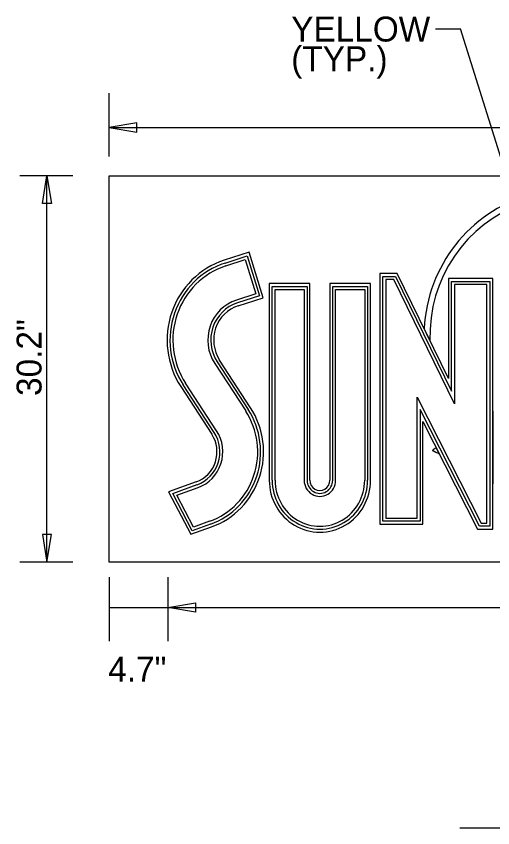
# Model space of a CAD drawing. Extents: x 10268197 to 10268738, y 2141503 to 2142677.
# Drawn here: x 10268621.93 to 10268635.31, y 2142399.46 to 2142422.24 of the extents above; entities that cross this region are included whole.
import ezdxf

# ---------------------------------------------------------------- set-up
doc = ezdxf.new("R2010")
doc.units = 0
for name, color, linetype in [('1', 7, 'Continuous'), ('Default', 7, 'Continuous'), ('GSDims', 7, 'Continuous')]:
    doc.layers.add(name, color=color, linetype=linetype)

msp = doc.modelspace()

# ---------------------------------------------------------------- linework, layer by layer
at = {"layer": '1'}
for p in [(10268633.707, 2142421.886), (10268636.311, 2142415.796)]:
    msp.add_line(p, (10268634.409, 2142421.886), dxfattribs=at)
at = {"layer": 'Default'}
for p, q in [((10268627.797, 2142415.309), (10268628.418, 2142415.51)), ((10268628.418, 2142415.51), (10268628.762, 2142414.392)), ((10268627.822, 2142415.23), (10268628.365, 2142415.405)), ((10268627.822, 2142415.23), (10268628.365, 2142415.405)), ((10268628.365, 2142415.405), (10268628.66, 2142414.447)), ((10268628.365, 2142415.405), (10268628.66, 2142414.447)), ((10268632.143, 2142415.013), (10268632.143, 2142407.978)), ((10268632.225, 2142408.062), (10268632.225, 2142414.929)), ((10268632.306, 2142414.845), (10268632.306, 2142408.146)), ((10268632.532, 2142414.845), (10268632.306, 2142414.845)), ((10268634.234, 2142411.355), (10268632.532, 2142414.845)), ((10268629.119, 2142409.212), (10268629.119, 2142414.655)), ((10268629.119, 2142414.655), (10268630.1, 2142414.655)), ((10268629.201, 2142409.212), (10268629.201, 2142414.572)), ((10268629.201, 2142414.572), (10268630.018, 2142414.572)), ((10268629.201, 2142409.212), (10268629.201, 2142414.572)), ((10268629.201, 2142414.572), (10268630.018, 2142414.572)), ((10268630.018, 2142414.572), (10268630.018, 2142409.212)), ((10268630.018, 2142414.572), (10268630.018, 2142409.212)), ((10268630.1, 2142414.655), (10268630.1, 2142409.212)), ((10268630.819, 2142409.212), (10268630.819, 2142414.655)), ((10268630.819, 2142414.655), (10268631.799, 2142414.655)), ((10268630.9, 2142409.212), (10268630.9, 2142414.572)), ((10268630.9, 2142414.572), (10268631.717, 2142414.572)), ((10268630.9, 2142409.212), (10268630.9, 2142414.572)), ((10268630.9, 2142414.572), (10268631.717, 2142414.572)), ((10268631.717, 2142414.572), (10268631.717, 2142409.212)), ((10268631.717, 2142414.572), (10268631.717, 2142409.212)), ((10268631.799, 2142414.655), (10268631.799, 2142409.212)), ((10268634.234, 2142414.711), (10268634.234, 2142411.355)), ((10268635.149, 2142414.711), (10268634.234, 2142414.711)), ((10268635.149, 2142408.012), (10268635.149, 2142414.711)), ((10268628.66, 2142414.447), (10268628.117, 2142414.271)), ((10268628.66, 2142414.447), (10268628.117, 2142414.271)), ((10268628.762, 2142414.392), (10268628.142, 2142414.191)), ((10268633.389, 2142413.463), (10268633.549, 2142413.136)), ((10268627.575, 2142412.54), (10268628.444, 2142411.203)), ((10268628.512, 2142411.25), (10268627.643, 2142412.586)), ((10268627.507, 2142412.493), (10268628.376, 2142411.157)), ((10268627.507, 2142412.493), (10268628.376, 2142411.157)), ((10268626.555, 2142411.843), (10268627.424, 2142410.506)), ((10268627.492, 2142410.553), (10268626.623, 2142411.89)), ((10268627.56, 2142410.599), (10268626.691, 2142411.936)), ((10268627.56, 2142410.599), (10268626.691, 2142411.936)), ((10268633.189, 2142408.146), (10268633.189, 2142411.542)), ((10268633.189, 2142411.542), (10268634.987, 2142408.012)), ((10268635.313, 2142411.156), (10268635.313, 2142409.116)), ((10268633.817, 2142409.946), (10268633.726, 2142410.126)), ((10268626.327, 2142408.844), (10268627.013, 2142409.089)), ((10268626.444, 2142408.798), (10268627.04, 2142409.01)), ((10268626.444, 2142408.798), (10268627.04, 2142409.01)), ((10268626.872, 2142407.797), (10268626.327, 2142408.844)), ((10268626.911, 2142407.9), (10268626.444, 2142408.798)), ((10268626.911, 2142407.9), (10268626.444, 2142408.798)), ((10268627.388, 2142407.982), (10268626.872, 2142407.797)), ((10268627.362, 2142408.061), (10268626.911, 2142407.9)), ((10268627.362, 2142408.061), (10268626.911, 2142407.9)), ((10268632.306, 2142408.146), (10268633.189, 2142408.146)), ((10268634.987, 2142408.012), (10268635.149, 2142408.012)), ((10268653.948, 2142406.917), (10268624.544, 2142406.917)), ((10268634.39, 2142399.458), (10268644.821, 2142399.458))]:
    msp.add_line(p, q, dxfattribs=at)
for points in [[(10268624.544, 2142406.917), (10268624.544, 2142417.76), (10268653.948, 2142417.76), (10268653.948, 2142406.917)], [(10268628.166, 2142414.112), (10268628.865, 2142414.338), (10268628.471, 2142415.615), (10268627.773, 2142415.389)], [(10268632.143, 2142407.978), (10268633.352, 2142407.978), (10268633.352, 2142410.859), (10268634.888, 2142407.844), (10268635.313, 2142407.844), (10268635.313, 2142414.879), (10268634.071, 2142414.879), (10268634.071, 2142412.065), (10268632.633, 2142415.013), (10268632.143, 2142415.013)], [(10268632.225, 2142414.929), (10268632.583, 2142414.929), (10268634.153, 2142411.71), (10268634.153, 2142414.795), (10268635.231, 2142414.795), (10268635.231, 2142407.928), (10268634.937, 2142407.928), (10268633.27, 2142411.2), (10268633.27, 2142408.062), (10268632.225, 2142408.062)], [(10268630.181, 2142409.212), (10268630.181, 2142414.739), (10268629.038, 2142414.739), (10268629.038, 2142409.212)], [(10268631.88, 2142409.212), (10268631.88, 2142414.739), (10268630.737, 2142414.739), (10268630.737, 2142409.212)], [(10268626.986, 2142409.168), (10268626.21, 2142408.891), (10268626.832, 2142407.695), (10268627.415, 2142407.903)]]:
    msp.add_lwpolyline(points, dxfattribs=at)
msp.add_lwpolyline([(10268634.234, 2142414.711), (10268634.234, 2142411.355), (10268632.532, 2142414.845), (10268632.306, 2142414.845), (10268632.306, 2142408.146), (10268633.189, 2142408.146), (10268633.189, 2142411.542), (10268634.987, 2142408.012), (10268635.149, 2142408.012), (10268635.149, 2142414.711)], close=True, dxfattribs=at)
for centre, major_axis, ratio, start_param, end_param in [((10268637.386, 2142413.254), (0, 4.102), 0.97582, 5.303349, 7.802858), ((10268637.386, 2142413.254), (0, 4.102), 0.97582, 5.303349, 7.802858), ((10268637.386, 2142413.254), (0, 3.935), 0.97582, 5.332201, 7.884008), ((10268637.386, 2142413.254), (0, 3.935), 0.97582, 5.332201, 7.884008), ((10268628.464, 2142413.147), (0, 2.351), 0.97582, 0.306207, 2.15869), ((10268628.464, 2142413.147), (0, 2.268), 0.97582, 0.306207, 2.15869), ((10268628.463, 2142413.147), (0, 2.184), 0.975477, 0.305879, 2.158799), ((10268628.463, 2142413.147), (0, 2.184), 0.975477, 0.305879, 2.158799), ((10268628.463, 2142413.147), (0, 1.179), 0.975477, 0.305879, 2.158799), ((10268628.463, 2142413.147), (0, 1.179), 0.975477, 0.305879, 2.158799), ((10268628.464, 2142413.147), (0, 1.095), 0.97582, 0.306207, 2.15869), ((10268628.464, 2142413.147), (0, 1.011), 0.97582, 0.306207, 2.15869), ((10268637.386, 2142413.252), (0, -3.935), 0.97582, 4.712389, 4.712389), ((10268626.7, 2142410.011), (0, -2.065), 0.975477, 0.334737, 2.158799), ((10268626.7, 2142410.011), (0, -2.065), 0.975477, 0.334737, 2.158799), ((10268626.699, 2142410.011), (0, 2.149), 0.97582, 3.476656, 5.300276), ((10268626.699, 2142410.011), (0, 2.233), 0.97582, 3.476656, 5.300276), ((10268626.699, 2142410.011), (0, 0.893), 0.97582, 3.476661, 5.300276), ((10268626.699, 2142410.011), (0, 0.977), 0.97582, 3.476661, 5.300276), ((10268626.7, 2142410.011), (0, -1.06), 0.975477, 0.334742, 2.158799), ((10268626.7, 2142410.011), (0, -1.06), 0.975477, 0.334742, 2.158799), ((10268641.439, 2142399.446), (0, 13.287), 0.97582, 0.637151, 0.647654), ((10268641.439, 2142399.446), (0, 13.287), 0.97582, 0.637152, 0.647654), ((10268626.675, 2142394.606), (0, 16.997), 0.97582, 5.837989, 5.851358), ((10268626.675, 2142394.606), (0, 16.997), 0.97582, 5.837989, 5.851358), ((10268630.459, 2142409.212), (0, 1.457), 0.97582, 1.570446, 4.71274), ((10268630.459, 2142409.212), (0, 1.373), 0.97582, 1.570446, 4.71274), ((10268630.459, 2142409.212), (0, -1.29), 0.975477, 4.712389, 7.853982), ((10268630.459, 2142409.212), (0, -1.29), 0.975477, 4.712389, 7.853982), ((10268630.459, 2142409.212), (0, -0.452), 0.975477, 4.712389, 7.853982), ((10268630.459, 2142409.212), (0, -0.452), 0.975477, 4.712389, 7.853982), ((10268630.459, 2142409.212), (0, 0.368), 0.97582, 1.570446, 4.71274), ((10268630.459, 2142409.212), (0, 0.285), 0.97582, 1.570446, 4.71274)]:
    msp.add_ellipse(centre, major_axis=major_axis, ratio=ratio, start_param=start_param, end_param=end_param, dxfattribs=at)
at = {"layer": 'GSDims'}
for p, q in [((10268624.544, 2142418.305), (10268624.544, 2142420.074)), ((10268624.544, 2142419.113), (10268653.948, 2142419.113)), ((10268623.527, 2142417.76), (10268622.036, 2142417.76)), ((10268622.797, 2142406.917), (10268622.797, 2142417.76)), ((10268623.527, 2142406.917), (10268622.036, 2142406.917)), ((10268624.544, 2142406.497), (10268624.544, 2142404.694)), ((10268626.195, 2142406.497), (10268626.195, 2142404.694)), ((10268624.544, 2142405.64), (10268626.195, 2142405.64)), ((10268626.195, 2142405.64), (10268652.243, 2142405.64))]:
    msp.add_line(p, q, dxfattribs=at)
for points in [[(10268624.544, 2142419.113), (10268625.319, 2142418.983), (10268625.319, 2142419.242)], [(10268622.797, 2142417.76), (10268622.926, 2142416.986), (10268622.668, 2142416.986)], [(10268622.797, 2142406.917), (10268622.926, 2142407.691), (10268622.668, 2142407.691)], [(10268626.195, 2142405.64), (10268626.97, 2142405.769), (10268626.97, 2142405.511)]]:
    msp.add_lwpolyline(points, close=True, dxfattribs=at)

# ---------------------------------------------------------------- texts
at = {"layer": '1'}
for s, p in [('YELLOW', (10268629.655, 2142421.528)), ('(TYP.)', (10268629.655, 2142420.696)), ('4.7"', (10268624.518, 2142403.561))]:
    msp.add_text(s, height=0.7, dxfattribs=at).set_placement(p)
msp.add_text('30.2"', height=0.7, rotation=90, dxfattribs=at).set_placement((10268622.645, 2142411.579))

doc.saveas('drawing.dxf')
